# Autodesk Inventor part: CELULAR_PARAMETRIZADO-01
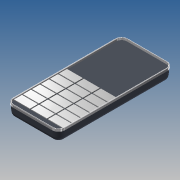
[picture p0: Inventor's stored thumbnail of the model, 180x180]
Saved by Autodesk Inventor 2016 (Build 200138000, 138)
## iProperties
Created: 2011-11
Part Number: CELULAR_PARAMETRIZADO-01
Material: ABS Plastic
Document SubType Name: Modeling
Designer: julian.chica
Mass: 104.172 g
Surface Area: 281.011 cm^2
Volume: 98.2755 cm^3
Density: 1.06 g/cm^3
Appearance: Plastic (White)
Author: julian.chica
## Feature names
1. Extrusion1
2. desmolde
3. Fillet1
4. Fillet2
5. Sweep1
6. Extrusion2
7. Rectangular Pattern1
## Parameters: ancho = 49.5 mm, d3 = 0, desmolde = -3 deg, redondeo_inferior = 6 mm, d6 = 4.5 mm, d7 = 0, ancho_tecla = 15.27871 mm, d10 = 0.7 mm, d11 = 0, dir1_pattern = 32.55742 mm, dir2_pattern = 8.63935 mm, alto_tecla = 7.63935 mm, d23 = 0.20628 mm, d24 = 1.03707 mm, d29 = 1.52959 mm, d30 = 1.90569 mm, ancho_total_teclado = 47.83613 mm, d32 = 0
